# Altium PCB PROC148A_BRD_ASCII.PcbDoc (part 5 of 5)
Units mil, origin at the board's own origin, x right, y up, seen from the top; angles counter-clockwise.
Board outline 7150 x 3764 mil, 4 copper layers (Top Layer, GND01, PWR/GND02, Bottom Layer), stack 60.96 mil thick; 312 components, 352 nets, 2206 pads, 423 vias.
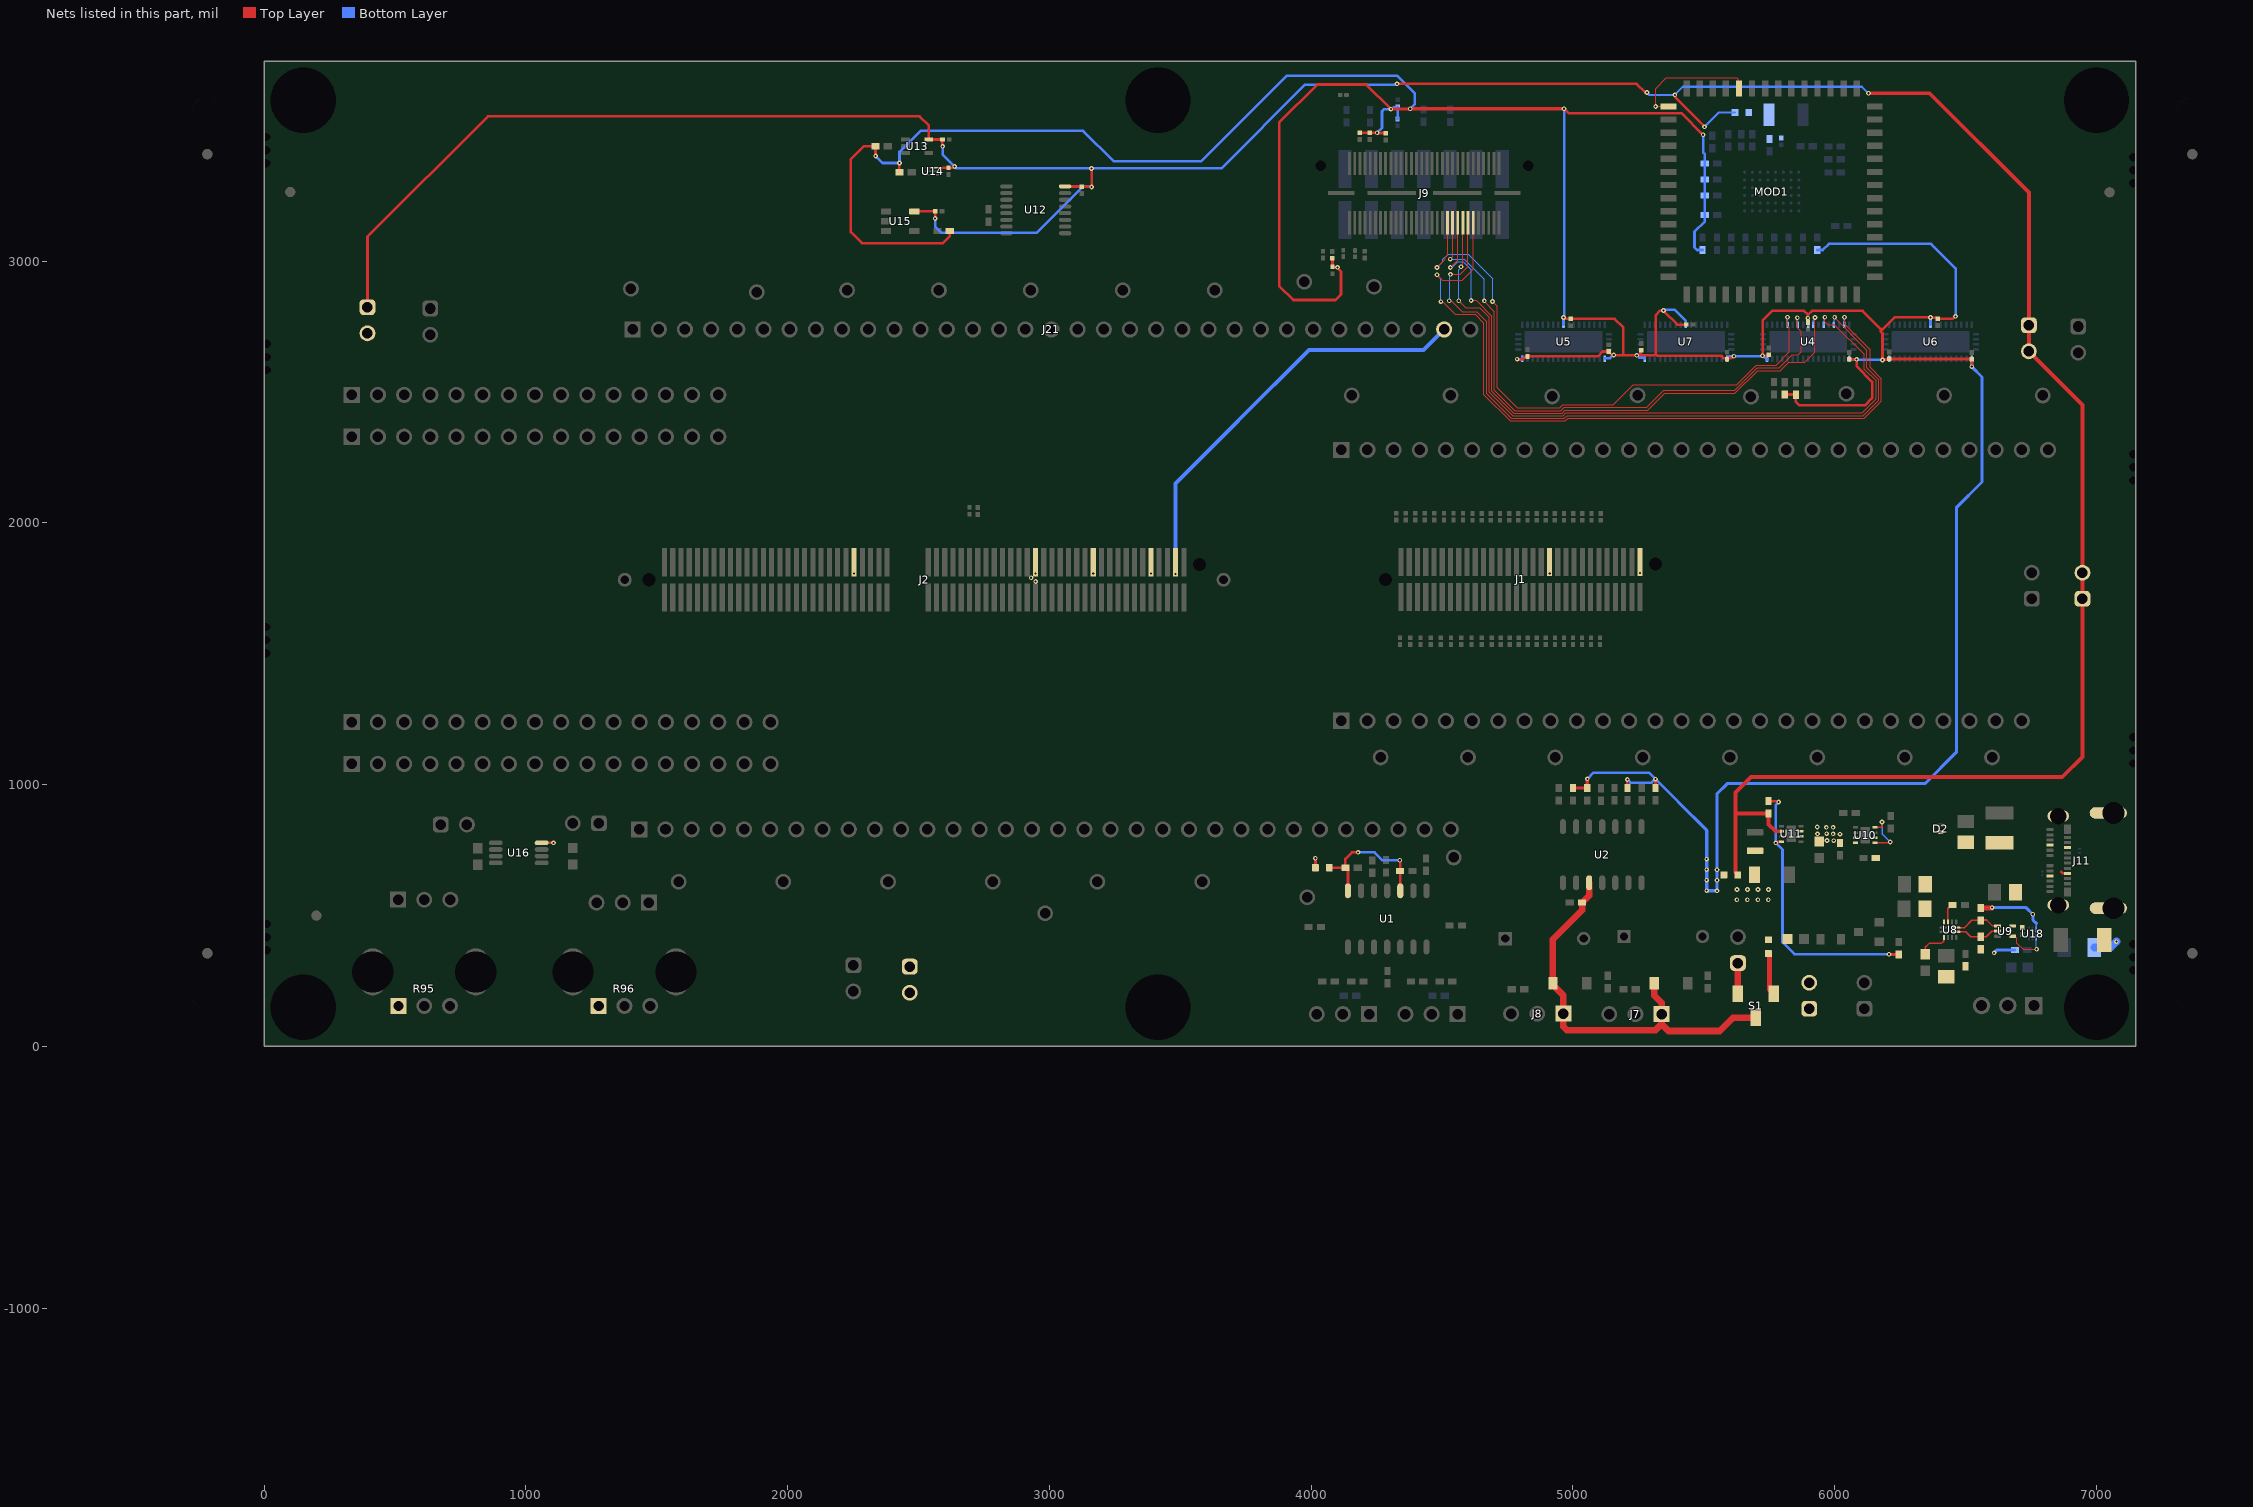
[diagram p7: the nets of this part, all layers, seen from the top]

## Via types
v1: diameter 18, hole 8, Top Layer to Bottom Layer, tented both sides, 422 vias
v2: diameter 18, hole 8, Top Layer to Bottom Layer, 1 vias

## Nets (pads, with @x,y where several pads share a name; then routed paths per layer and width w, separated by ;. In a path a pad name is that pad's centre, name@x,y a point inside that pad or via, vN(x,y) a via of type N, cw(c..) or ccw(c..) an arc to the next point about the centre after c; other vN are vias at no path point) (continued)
TRC_DATA10_MUX: J9.39 U4.26 | length 2289.2
  Top Layer w4: v1(4481,2975.65) 4512.4,3007.05 4512.4,3015.38 4520.86,3023.84 J9.39@4520.86,3147.3 ; v1(4692.97,2845.6) 4710.24,2828.33 4710.24,2516.39 4786.96,2439.67 4950.47,2439.67 4961.93,2451.13 5153.58,2451.13 5230.29,2527.84 5625.99,2527.84 5700.86,2602.71 5775.82,2602.71 5826.31,2653.2 5826.31,2745.54 5819.6,2752.25 v1(5819.6,2785.7)
  Bottom Layer w4: v1(4481,2975.65) 4503.64,2998.29 4503.64,3006.62 4523.45,3026.43 4599.71,3026.43 4692.97,2933.17 v1(4692.97,2845.6) ; v1(5819.6,2785.7) 5819.6,2757.22 U4.26@5819.98,2756.84
TRC_DATA11_MUX: J9.41 U4.28 | length 2207.2
  Top Layer w4: v1(4531.27,3007.56) 4540.54,3016.83 J9.41@4540.54,3147.3 ; v1(4661.71,2848.05) 4661.71,2845.87 4700.24,2807.34 4700.24,2506.53 4777.52,2429.25 4954.19,2429.25 4966.07,2441.13 5281.06,2441.13 5346.41,2506.48 5618.21,2506.48 5702.5,2590.77 5703.66,2590.77 5704.66,2591.77 5788.2,2591.77 5838.08,2641.65 5860.82,2641.65 5872.37,2653.2 5872.37,2730.56 5857.4,2745.53 v1(5857.4,2783.8)
  Bottom Layer w4: v1(4531.27,3007.56) 4584.46,3007.56 4661.71,2930.31 v1(4661.71,2848.05) ; v1(5857.4,2783.8) 5857.4,2758.79 U4.28@5859.35,2756.84
TRC_DATA12_MUX: J9.43 U4.31 | length 2321
  Top Layer w4: v1(4531.54,2975.48) 4560.23,3004.17 J9.43@4560.23,3147.3 ; v1(4611.25,2849.56) 4630.51,2849.56 4690.24,2789.83 4690.24,2502.38 4773.36,2419.25 4958.34,2419.25 4969.12,2430.04 5285.86,2430.04 5350.34,2494.52 5618.98,2494.52 5706.23,2581.77 5792.34,2581.77 5823.55,2612.97 5885,2612.97 5924.48,2652.45 v1(5924.48,2784.53)
  Bottom Layer w4: v1(4531.54,2975.48) 4537.21,2975.48 4559.05,2997.32 4580.56,2997.32 4611.25,2966.63 v1(4611.25,2849.56) ; U4.31@5918.4,2756.84 5918.4,2774.66 5924.48,2780.74 v1(5924.48,2784.53)
TRC_DATA13_MUX: J9.45 U4.33 | length 2716
  Top Layer w4: v1(4563.67,2848.76) 4591.07,2821.36 4644.57,2821.36 4680.24,2785.69 4680.24,2498.24 4769.22,2409.25 4962.48,2409.25 4973.27,2420.04 6104.65,2420.04 6158.12,2473.51 6158.12,2542.55 6112.81,2587.85 6112.81,2643.86 5999.17,2757.5 5973.23,2757.5 5962.23,2768.51 v1(5962.23,2785.71) ; v1(4572.74,2978.45) 4579.91,2985.62 J9.45@4579.91,3147.3
  Bottom Layer w4: v1(4563.67,2848.76) 4563.67,2966.31 4572.74,2975.38 v1(4572.74,2978.45) ; U4.33@5957.77,2756.84 5960,2759.07 5960,2783.48 v1(5962.23,2785.71)
TRC_DATA14_MUX: J9.47 U4.35 | length 2783.9
  Top Layer w4: v1(4527.39,2848.76) 4530.07,2846.08 4537.7,2846.08 4576.44,2807.34 4631.69,2807.34 4670.24,2768.79 4670.24,2493.53 4764.52,2399.25 4966.62,2399.25 4977.41,2410.04 6108.79,2410.04 6168.12,2469.37 6168.12,2546.69 6122.71,2592.1 6122.71,2660.15 5999.98,2782.87 v1(5999.98,2785.71) ; v1(4532.45,2949.48) 4570.46,2949.48 4598.68,2977.7 4598.68,3146.39 J9.47@4599.6,3147.3
  Bottom Layer w4: v1(4527.39,2848.76) 4529.92,2851.29 4529.92,2946.95 v1(4532.45,2949.48) ; U4.35@5997.14,2756.84 5998.56,2758.26 5998.56,2784.29 v1(5999.98,2785.71)
TRC_DATA15_MUX: J9.49 U4.37 | length 2922.5
  Top Layer w4: v1(4480.7,2947.99) 4500.98,2927.71 4577.85,2927.71 4619.28,2969.13 J9.49@4619.28,3147.3 ; v1(4495.56,2845.27) 4498.24,2842.59 4504.17,2842.59 4550.59,2796.18 4627.28,2796.18 4660.24,2763.22 4660.24,2489.39 4760.37,2389.25 4970.76,2389.25 4981.55,2400.04 6112.93,2400.04 6178.16,2465.27 6178.16,2550.79 6134.84,2594.11 6134.84,2662.16 6037.73,2759.26 v1(6037.73,2785.71)
  Bottom Layer w4: v1(4480.7,2947.99) 4495.56,2933.13 v1(4495.56,2845.27) ; U4.37@6036.51,2756.84 6037.12,2757.45 6037.12,2785.1 v1(6037.73,2785.71)
TUSB_EN_N: R53.2 U8.11 | length 74.7
  Top Layer w6: U8.11@6432.72,475.46 6432.13,476.06 6432.13,525.7 6446.45,540.03 R53.2@6450.39,540.03
TUSB_OUT1: R50.2 U8.8 U9.1 | length 177.3
  Top Layer w6: U8.8@6466.18,453.81 6495.81,453.81 6523.57,481.57 R50.2@6557.59,481.57 6559.08,483.06 6580,483.06 6602.69,460.37 U9.1@6622,460.37
TUSB_OUT2: R49.2 U8.7 U9.2 | length 172.7
  Top Layer w6: U8.7@6466.18,438.06 6500.87,438.06 6520,418.94 R49.2@6557.59,418.94 6578.94,418.94 6599.81,439.81 6621.13,439.81 U9.2@6622,440.68
TUSB_PORT: R52.1 U8.3 | length 122.2
  Top Layer w6: R52.1@6346,351.69 6346,379 6360.43,393.43 6408.4,393.43 6416.97,402 U8.3@6416.97,416.41
USBC_EARTH: C34.2 J11.1 J11.2 J11.3 J11.4 R57.1 | length 93.7
  Bottom Layer w30: R57.1@6991.8,377.36 7053.06,377.36 v1(7076,400.31)
USBC_EN: U9.4 U18.1 | length 167.5
  Top Layer w4: U9.4@6680.27,421 6687.55,421 6696.09,412.46 6696.09,394.42 6719.36,371.15 v1(6771.35,371.15)
  Bottom Layer w4: U18.1@6769.74,415.65 6770.54,414.85 6770.54,371.96 v1(6771.35,371.15)
VBAT_LIN: J4.1 S1.3 | length 118.1
  Top Layer w4: J4.1@5629.32,317.2 J4.1@5630.35,318.23
  Top Layer w25: S1.3@5629.32,200.55 J4.1@5629.32,317.2
VBUS_USBC: C8.1 C26.1 C27.1 C28.1 C29.1 C35.1 C43.1 D2.1 J11.A4 J11.A9 J11.B4 J11.B9 R49.1 R50.1 R51.1 R54.1 R94.1 U8.12 U9.5 U10.1 U10.2 U10.4 U18.6 | length 576.2
  Top Layer w6: U10.1@6154.22,777.71 6208.85,777.71 v1(6212.26,781.12) ; U10.4@6154.22,836.76 6175.76,836.76 6181,842 v1(6181,857)
  Top Layer w10: 6865,667.26 6870.57,661.69 6887.95,661.69 J11.B9@6888.86,660.79
  Top Layer w20: R50.1@6557.59,528.82 6599.96,528.82 v1(6601.3,530.16)
  Bottom Layer w6: v1(6181,857) 6181,812.38 v1(6212.26,781.12) ; U18.6@6769.74,447.15 6769.74,470.41
  Bottom Layer w12: v1(6601.3,530.16) 6731.27,530.16 6757.63,503.8 6757.63,482.52 6769.74,470.41 ; v1(6609.26,357.37) 6620.89,369 R94.1@6688.67,369
  other v1: 6756.48,504.95
VCC_3V3_IO: C11.1 C12.1 C13.1 C14.1 C15.1 C16.1 C17.1 C18.1 C19.1 C20.1 C21.1 C22.1 C23.1 C24.1 C25.1 FB4.2 R13.2 R14.2 R15.2 R16.2 R17.2 R23.2 R73.2 R74.2 R75.2 R76.2 R77.2 R78.2 R79.2 R80.2 R83.2 R85.2 R86.2 R87.1 R90.1 U4.1 U4.17 U4.30 U5.1 U5.17 U5.30 U6.1 U6.17 U6.30 U7.1 U7.17 U7.30 | length 16744.5
  Top Layer w10: v1(2336.34,3401.46) 2335.67,3402.13 R79.2@2335.67,3438.96 2290.93,3438.96 2241.53,3389.56 2241.53,3110.92 2283.54,3068.91 2592.94,3068.91 2619.65,3095.62 R83.2@2619.65,3115.05 ; R80.2@2427.05,3339.55 2427.05,3374.71 v1(2427.33,3374.99) ; R15.2@4081.19,3011.2 4081.44,3010.95 4081.44,2978.4 C24.1@4081.68,2978.15 4083.69,2976.14 v1(4100.52,2976.14) 4100.52,2973.98 4114.21,2960.29 4114.21,2872.68 4092.84,2851.31 3932.04,2851.31 3878.03,2905.32 3878.03,3529.44 4023.48,3674.89 4210.24,3674.89 v1(4304.51,3580.61) 4305.21,3581.31 4377.71,3581.31 v1(4378.4,3582) ; R17.2@4186.1,3490.5 R16.2@4223.99,3490.5 v1(4252.03,3490.5) 4253.01,3489.52 4283.9,3489.52 C23.1@4284.88,3488.54 ; v1(4786.87,2625.65) 4809.79,2625.65 4823.17,2639.03 C15.1@4826.2,2636 ; C15.1@4826.52,2636.32 5094.83,2636.32 5113.06,2654.56 C14.1@5137.39,2654.56 5137.39,2653.77 5148.04,2643.12 5154.5,2643.12 v1(5156.03,2641.59) 5157.19,2640.43 5180.03,2640.43 5180.56,2639.9 5191.52,2639.9 ; v1(4964.3,2785) 4969.12,2780.18 4991.7,2780.18 C16.1@4991.7,2779.39 5159.51,2779.39 5191.52,2747.38 5191.52,2639.9 ; v1(4966.12,3582) 4967.14,3582 4983.6,3565.54 5414.61,3565.54 v1(5497.44,3482.71) ; R87.1@5207.87,987.24 v1(5207.87,1019.88) ; C21.1@5261.18,2659.51 5257.91,2656.24 5257.91,2645.31 v1@5252.5,2639.9 ; R85.2@5315.34,987.24 v1(5315.34,1020.91) ; C22.1@5433.11,2757.6 5398.92,2757.6 5346.18,2810.34 v1(5346.18,2811.74) 5344.95,2810.51 5333.47,2810.51 5315.95,2792.99 5315.95,2645.99 ; C20.1@5588.8,2625.41 C20.1@5588.8,2626.2 ; v1(5614.7,2636.7) 5612.54,2636.7 5605.3,2629.46 5592.07,2629.46 C20.1@5588.8,2626.2 ; C12.1@5748.48,2641.86 5748.48,2641.59 5745.21,2638.32 v1(5724.52,2638.32) 5724.52,2773.52 5761.22,2810.22 5883.42,2810.22 5897.5,2796.14 v1(5897.5,2782) 5897.6,2781.9 5897.6,2765.49 C13.1@5897.7,2765.39 ; R13.2@5809.01,2490.38 5850.97,2490.38 R14.2@5851.61,2489.74 5851.61,2462.26 5864.83,2449.04 6115.26,2449.04 6143.4,2477.18 6143.4,2538.88 6083.72,2598.56 v1(6083.72,2624.73) 6083.09,2625.36 C11.1@6056.15,2625.36 ; 5898.32,2795.12 5913.43,2810.22 6106.18,2810.22 6175.33,2741.07 6175.33,2731.43 ; v1(6461.72,2789.05) 6459.56,2789.05 6450.27,2779.76 C19.1@6393.6,2779.76 6390.34,2783.03 6370.34,2783.03 6368.37,2785 v1(6366.2,2785) 6228.9,2785 6175.33,2731.43 ; v1@6523.45,2596.75 C17.1@6523.45,2625.36 6522.69,2626.12 6209.34,2626.12 C18.1@6208.57,2626.89 6205.62,2623.94 6184.11,2623.94 v1(6182.58,2622.41) 6182.58,2724.18 6175.33,2731.43 ; 5191.52,2639.9 v1(5243.77,2639.9) v1@5252.5,2639.9 ; v1@5252.5,2639.9 5309.86,2639.9 5315.95,2645.99 ; 5315.95,2645.99 5323.28,2638.65 5567.66,2638.65 5567.66,2637 5575.2,2629.46 5588.8,2629.46 C20.1@5588.8,2626.2
  Top Layer w12: v1(4378.4,3582) v1(4966.12,3582) ; R90.1@4999.88,986.78 R86.2@5054.88,986.78 v1(5054.88,1022.39)
  Bottom Layer w10: v1(2336.34,3401.46) 2362.81,3374.99 v1(2427.33,3374.99) 2427.33,3417.41 2507.91,3497.99 3129.14,3497.99 3245.53,3381.6 3580.15,3381.6 3906.8,3708.25 4328.32,3708.25 4395.28,3641.29 4395.28,3598.88 v1(4378.4,3582) ; v1(4252.03,3490.5) 4270.72,3509.19 4270.72,3572.18 4279.15,3580.61 v1(4304.51,3580.61) ; v1@4306.68,3580.61 v1(4304.51,3580.61) ; R23.2@4329.6,3542.98 4330.16,3543.54 C25.1@4330.16,3589.58 ; C25.1@4330.71,3590.13 C25.1@4330.16,3589.58 ; v1(4786.87,2625.65) 4806.64,2625.65 U5.17@4806.64,2626.92 U5.17@4806.64,2633.65 ; U5.30@4964.12,2756.84 4964.12,2784.82 v1(4964.3,2785) 4966.12,2786.82 v1(4966.12,3582) ; v1(5054.88,1022.39) 5078.25,1045.76 5290.49,1045.76 v1(5315.34,1020.91) ; U5.1@5121.6,2626.92 5121.6,2629.32 5121.68,2629.4 5141.68,2629.4 5153.87,2641.59 v1(5156.03,2641.59) ; v1(5207.87,1019.88) 5220.08,1007.68 5299.94,1007.68 5313.17,1020.91 v1(5315.34,1020.91) ; v1(5243.77,2639.9) 5245.93,2639.9 5253.86,2631.98 5273.86,2631.98 5273.94,2631.9 U7.17@5273.94,2626.92 ; v1(5346.18,2811.74) 5347.71,2813.27 5353.37,2813.27 5354.92,2814.83 5387.54,2814.83 5431.34,2771.02 5431.34,2756.92 U7.30@5431.42,2756.84 ; 5404.4,931.85 v1(5315.34,1020.91) ; R78.2@5495.22,3042.66 5473.73,3042.66 5464.23,3052.16 5464.23,3112.48 5503.9,3152.15 R73.2@5503.9,3176.5 5504,3176.6 R75.2@5504,3250.4 R77.2@5504,3311.9 R76.2@5504,3373.4 5504,3409.39 5497.68,3415.71 v1@5497.68,3482.47 ; U7.1@5588.9,2626.92 5598.68,2636.7 v1(5614.7,2636.7) 5614.95,2636.95 5723.15,2636.95 v1(5724.52,2638.32) 5726.06,2638.32 5741.16,2623.22 5741.24,2623.3 U4.17@5741.24,2626.92 ; v1(5897.5,2782) 5898.64,2780.86 5898.64,2756.92 U4.30@5898.72,2756.84 ; R74.2@5933.53,3042.66 5953.98,3042.66 5977.32,3066 6368.1,3066 6461.72,2972.38 v1(6461.72,2789.05) ; U4.1@6056.2,2626.92 6058.39,2624.73 v1(6083.72,2624.73) 6084.88,2623.57 6181.42,2623.57 v1(6182.58,2622.41) 6184.11,2623.94 6208.46,2623.94 6208.54,2624.02 U6.17@6208.54,2626.92 ; U6.30@6366.02,2756.84 6366.02,2784.82 v1(6366.2,2785) ; v1(4304.51,3580.61) 4306.04,3582.14 4309.4,3582.14 4314.79,3587.53 4328.11,3587.53 C25.1@4330.16,3589.58
  Bottom Layer w12: 5404.4,931.85 5511,825.25 v1(5511,715.45) v1(5511,675.3) v1(5511,635.15) v1(5511,595) 5511.23,594.77 5549.77,594.77 v1(5550,594.55) v1(5550,634.7) v1(5550,674.85) 5550,964.49 5589.67,1004.16 6344.95,1004.16 6464.79,1124 6464.79,2058.51 6562.71,2156.43 6562.71,2557.49 v1(6523.5,2596.7) U6.1@6523.5,2626.92
VCC_3V3_PG: R56.2 R58.2 U11.8 | length 1079.4
  Top Layer w10: R58.2@5746.82,937.2 5782.68,937.2 v1(5785.82,934.06) ; v1(5774.91,777.66) 5779.72,782.47 5796.93,782.47 U11.8@5797.01,782.55
  Top Layer w12: v1(6207.67,352.27) 6208.56,351.38 R56.2@6245,351.38
  Bottom Layer w10: v1(5785.82,934.06) 5774.91,923.15 v1(5774.91,777.66) 5800.41,752.16 5800.41,398.18 5846.32,352.27 v1(6207.67,352.27)
VCC_3V3_SYS: C32.1 C37.1 C38.1 C39.1 C40.1 FB3.1 FB4.1 J16.1 J16.2 J23.1 J23.2 J28.1 J28.2 J29.1 J29.2 L1.2 R58.1 R95.1 R96.1 U11.6 U12.16 U13.5 U14.6 U15.5 U16.8 | length 12871.6
  Top Layer w6: U14.6@2569.29,3357.11 2590.86,3357.11
  Top Layer w10: J28.1@395,2824 395,3093.44 395.17,3093.27 854.84,3552.94 2504.68,3552.94 2539.29,3518.33 U13.5@2539.29,3464.55 C38.1@2591.3,3464.55 2591.3,3439.37 v1(2592.36,3438.31) ; U16.8@1060.36,777.89 v1(1105.51,777.89) ; U15.5@2483.91,3189.17 U15.5@2484.29,3189.55 2484.79,3190.05 2563.47,3190.05 2563.97,3190.55 2563.97,3163 v1(2563.64,3162.67) ; 2590.86,3357.11 C39.1@2614.29,3357.11 ; C39.1@2614.73,3356.67 2633.29,3356.67 v1(2637.94,3361.32) ; U12.16@3060.12,3285.5 3060.58,3285.03 3123.72,3285.03 C37.1@3124.18,3284.57 3160.4,3284.57 v1(3161.53,3283.44) 3161.53,3353.58 v1(3161.02,3354.09) ; v1(4328.32,3677.32) 5243.5,3677.32 5277.04,3643.78 v1(5282.63,3643.78) ; v1(5389.48,3635.26) 5391.01,3633.73 5391.01,3625.95 5502.79,3514.17 v1(5502.79,3512.97)
  Top Layer w12: C39.1@2614.29,3357.11 C39.1@2614.73,3356.67
  Top Layer w15: FB4.1@5630,655 5621.12,663.88 5621.12,888.25 ; U11.6@5797.01,821.92 5773.08,821.92 5746.82,848.18 R58.1@5746.82,889.95 5622.83,889.95 5621.12,888.25 ; v1(6129.13,3641.22) 6362.28,3641.22 6741.81,3261.69 J23.1@6741.81,2755.22 J23.2@6741.81,2655.22 6946.42,2450.61 J16.2@6946.42,1809.98 J16.1@6946.42,1709.98 6946.42,1106.42 6869.3,1029.3 5681,1029.3 5621.12,969.42 5621.12,888.25
  Bottom Layer w8: v1(5282.63,3643.78) 5291.15,3635.26 v1(5389.48,3635.26) 5420.22,3666 6104.03,3666 6128.81,3641.22 v1(6129.13,3641.22) ; v1(5502.79,3512.97) 5557.64,3567.82 FB3.1@5618.92,3567.82
  Bottom Layer w10: v1(2563.64,3162.67) 2563.64,3131.59 2586.95,3108.28 2950.75,3108.28 3125.91,3283.44 v1(3161.53,3283.44) ; v1(2592.36,3438.31) 2592.36,3406.9 v1(2637.94,3361.32) 2645.17,3354.09 v1(3161.02,3354.09) 3657.3,3354.09 3977.36,3674.15 4325.15,3674.15 v1(4328.32,3677.32)
  other v1: 5626,560.53 5666.15,560.53 5706.3,560.53 5746.45,560.53 5626.45,599.53 5666.6,599.53 5706.76,599.53 5746.91,599.53
VCC_5V0_LIN: FB6.2 S1.1 | length 162.6
  Top Layer w20: FB6.2@5746.82,354.73 5750.43,351.12 5750.43,217.24 S1.1@5767.12,200.55
VCC_5V0_MCAN: C1.1 C2.1 FB5.2 U1.3 U1.7 | length 536.8
  Top Layer w10: FB5.2@4069.6,682.92 C2.1@4130.78,682.92 ; U1.7@4140.64,594.55 4140.64,676.11 4133.83,682.92 C2.1@4130.78,682.92 ; v1(4179.45,741.31) 4155.95,741.31 4130.78,716.14 C2.1@4130.78,682.92 ; v1(4338.57,711.11) 4339.68,710 C1.1@4339.68,670.72 4340.64,669.76 U1.3@4340.64,594.55
  Bottom Layer w10: v1(4179.45,741.31) 4242.55,741.31 4272.75,711.11 v1(4338.57,711.11)
VDD_3V3_PSRAM: C9.1 C10.1 FB3.2 R11.2
VDD_3V3_SYS: MOD1.1 MOD1.52 | length 488.8
  Top Layer w4: MOD1.1@5365.59,3590.66 v1(5315.93,3590.66) 5315.93,3658.73 5357.41,3700.21 5625.11,3700.21 5634.29,3691.03 MOD1.52@5634.29,3659.36 MOD1.52@5634.26,3659.31
VLIN: C5.1 D1.2 D6.2 J7.1 J8.1 S1.2 U2.10 | length 1572.5
  Top Layer w25: U2.10@5061.97,625.17 5061.97,576.18 C5.1@5035.1,549.3 5035.1,520.39 4923.75,409.04 D6.2@4923.75,240.72 4923.75,234.72 4963.69,194.78 J8.1@4963.69,125 4963.69,74.81 4976,62.5 5315.7,62.5 5338.62,85.42 ; D1.2@5310,240.72 5310,195.2 5338.62,166.58 J7.1@5338.62,123.66 5338.62,85.42 ; S1.2@5698.22,110 5611.52,110 5560.52,59 5365.04,59 5338.62,85.42
VMAIN: C33.2 C36.1 FB5.1 FB6.1 J1.158 J1.180 J2.48 J2.84 J2.98 J2.112 J2.118 J19.1 J19.2 J21.32 R55.2 U10.7 U10.8 U11.2 U11.3 | length 1957.3
  Top Layer w10: v1(2254.01,1805.95) J2.48@2254.01,1849.59 ; v1(2946.93,1805.95) J2.84@2946.93,1849.59 ; v1(3167.4,1805.95) J2.98@3167.4,1849.59 ; v1(3387.87,1805.95) J2.112@3387.87,1849.59 ; v1(3481.94,1805.53) 3481.94,1849.17 J2.118@3482.36,1849.59 ; v1(4016.15,718.78) 4016.45,718.48 FB5.1@4016.45,682.92 ; J1.158@4910.24,1850.93 4911.46,1849.71 v1(4911.46,1806.06) ; v1(5256.69,1809.1) J1.180@5256.69,1850.93
  Bottom Layer w15: v1(3481.94,1805.53) 3481.94,2151.08 3720.63,2389.77 3720.63,2390.15 3991.18,2660.7 4429.65,2660.7 J21.32@4507.95,2739
  other v1: 5996.19,786 5970.19,787 6020.19,811 5934.19,812 5994.19,812 5969.19,813 5968.19,837 5994.19,837 5933.19,838 2947.52,1776.44 2930.37,1790.33
pads on no net: D2.1S D2.2S Designator2. Designator2_1. Designator3. Designator3_1. Designator4. Designator4_1. Designator5. Designator5_1. Designator59_3_1_2. Designator59_3_1_2_1. Designator59_3_1_2_2. Designator59_3_1_2_3. Designator64_2_1_2. Designator64_2_1_2_1. Designator64_2_1_2_2. Designator64_2_1_2_3. Designator69_2. Designator69_2_1. Designator69_2_2. Designator69_2_3. FID1.1 FID2.1 FID3.1 FID4.1 FID5.1 FID6.1 J1.61 J1.62 J2.1 J2.2 J2.4 J2.181 J2.182 J2.185 J2.186 J9.8 J9.9 J9.10 J9.11 J9.14 J9.18 J9.20 J9.22 J9.24 J9.26 J9.28 J9.30 J9.32 J9.34 J9.36 J9.38 J9.40 J9.42 J9.44 J9.46 J9.48 J9.50 J9.51 J9.52 J9.53 J9.54 J9.55 J9.56 J9.59 J9.60 J9.MH1 J9.MH2 J10.2 J10.6 J10.13 J10.14 J11.A2 J11.A3 J11.A6 J11.A7 J11.A8 J11.A10 J11.A11 J11.B2 J11.B3 J11.B6 J11.B7 J11.B8 J11.B10 J11.B11 MHNP1. MHNP2. MHNP3. MHNP4. MHNP5. MHNP6. MOD1.53 R95.4 R95.5 R96.4 R96.5 SH-J1.0 SH-J2.0 SH-J3.0 SH-J4.0 SW3.1 U2.6 U2.11 U2.12 U2.14 U4.39 U4.41 U5.18 U5.20 U5.22 U5.24 U5.26 U5.28 U5.31 U5.33 U5.35 U5.37 U5.40 U5.42 U6.18 U6.20 U6.22 U6.24 U6.26 U6.28 U6.31 U6.33 U6.35 U6.37 U6.40 U6.42 U7.18 U7.20 U7.22 U7.24 U7.26 U7.28 U8.5 U8.9 U11.9@5834.41,794.36 U11.9@5834.41,829.79 U12.5 U12.6 U12.10 U12.11 U12.13 U12.14 U13.1 U14.5 U18.5

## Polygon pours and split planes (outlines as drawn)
GND on Top Layer "Top Layer-GND 4" (solid, remove dead copper, pour order 13): 3.15,3762.2 3.15,0 7151.02,0 7151.02,3761.81 3.94,3761.81
VMAIN on Top Layer "Top Layer-VMAIN 2" (solid, remove dead copper, pour order 12): 2235.62,1933.47 2235.62,1777 2248.69,1763.93 2249.36,1764.6 2974.91,1764.6 2974.91,1804.77 2964.47,1815.21 2278.73,1815.21 2271.55,1822.39 2271.55,1933.47
GND on Top Layer "Top Layer-GND 3" (solid, pour order 11): 6789.29,413.64 6789.29,310.65 6922.42,310.65 6922.42,441.03 6911.46,451.99 6815.17,451.99 6789.29,426.11
VBUS_USBC on Top Layer "Top Layer-VBUS_USBC 1" (solid, remove dead copper, pour order 10): 6624.6,319.02 6688.03,382.45 6688.03,507.05 6587.4,507.05 6589.78,391.78 6588.95,392.61 6543.97,392.61 6530.13,378.77 6530.13,336.27 6516.77,322.91 6483.17,322.91 6452.84,292.58 6386.67,292.58 6385.29,291.06 6385.29,212.49 6559.73,212.49 6624.6,277.36
GND on Top Layer "Top Layer-GND 1" (solid, pour order 9): 6930,607.93 6929.93,608 6854.93,608 6844.82,597.89 6805.03,597.89 6792.77,610.15 6772.06,610.15 6760,598.08 6760,571.59 6769.59,562 6794.44,562 6812.44,580 6868.26,580 6878.26,570 6927.24,570 6941,583.76 6941,601 6935,607
VMAIN on Top Layer "Top Layer-VMAIN 1" (solid, pour order 8): 5718,385 5771.01,385 5787.14,368.87 5787.14,304.86 5832.41,259.59 5832.41,80 5968.19,80 5968.19,249.81 5843,375 5843,447.81 5718,447.81
GND on Top Layer "Top Layer-GND 2" (solid, pour order 7): 6930,812.07 6929.93,812 6854.93,812 6844.82,822.11 6805.03,822.11 6792.77,809.86 6772.06,809.86 6760,821.92 6760,848.41 6769.59,858 6794.44,858 6812.44,840 6868.26,840 6878.26,850 6927.24,850 6941,836.24 6941,819 6935,813
GND on Top Layer "Top Layer-GND" (solid, remove dead copper, pour order 6): 5800,562 5871.81,562 5966.93,466.88 6133.86,466.88 6295.82,466.88 6300,471.06 6300,650 6294.58,655.42 6136.5,655.42 6133.86,658.06 6133.86,848.76 6154.11,869.02 6251.11,869.02 6284.11,836.02 6715,836.02 6715,959.02 6100,959.02 6100,755.66 6085.98,741.64 5904.29,741.64 5890,755.75 5890,779.94 5879.94,790 5855,790 5855,833.73 5884.36,833.73 5884.97,834.34 5884.97,853.41 5884.36,854.02 5785.54,854.02 5784.47,852.94 5784.47,832.83 5815,832.5 5815,780.62 5800,765.62
VCC_3V3_IO on Top Layer "Top Layer-VCC_3V3_IO" (solid, pour order 5): 5593,750 5489,750 5489,558 5593,558
VCC_3V3_SYS on Top Layer "Top Layer-VCC_3V3_SYS" (solid, remove dead copper, pour order 4): 5610,778 5610,551 5756.83,551 5756.83,778
NetL1_1 on Top Layer "Top Layer-NetL1_1" (solid, pour order 3): 5807,794.13 5806.87,794 5662,794 5649,807 5649,841 5663,855 5729,855 5774,810 5808,810 5811,807 5811,794.13
USBC_EARTH on Top Layer "Top Layer-USBC_EARTH" (solid, pour order 2): 6948.91,456.09 6927,478 6809,478 6783.54,503.46 6783.54,551.54 6801,569 6941,569 6964,592 6964,836 6942,858 6808,858 6792,874 6792,941 6823,972 7090,972 7122,940 7122,315 7107,300 6952.49,300 6948.91,303.58
VMAIN on Top Layer "Top Layer-VMAIN" (solid, pour order 1): 5992.36,852.94 5927.51,852.94 5903.15,828.58 5890,828.58 5859.57,828.58 5859.57,795.89 5884.41,795.89 5924.57,755.73 6089.57,755.73 6089.57,804.35 6040.95,804.35
VBUS_USBC on Top Layer "Top Layer-VBUS_USBC" (solid, remove dead copper, pour order 0): 6773.54,493.71 6773.54,637.24 6783.54,647.24 6849.05,647.24 6862.85,661.03 6910,661.03 6910,675.14 6857.11,675.14 6847.27,665.29 6801.03,665.29 6775,691.32 6775,767.24 6860,767.24 6870,757.24 6910,757.24 6910,777.24 6870,777.24 6862.77,784.47 6722.77,784.47 6680,827.24 6270,827.24 6250,807.24 6140,807.24 6140,678 6315,678 6315,466 6421,466 6421,637.24 6650,637.24 6660,627.24 6660,454 6667,447 6724.12,447 6724.12,493.71
GND on Bottom Layer "Bottom Layer-GND 2" (solid, remove dead copper, pour order 22): 1.1,3764 7145.98,3764 7145.98,1.57 0.71,1.57 0.71,3760.63
VCC_3V3_IO on Bottom Layer "VCC_3V3_IO_L04_P021" (solid, remove dead copper, pour order 21): 5423.98,836.59 5566.51,836.59 5566.51,574.32 5423.03,574.32 5423.03,607.59
VCC_3V3_IO on Bottom Layer "VCC_3V3_IO_L04_P020" (solid, remove dead copper, pour order 20): 4287.44,3600.34 4287.44,3533.51 4388.61,3533.51 4388.61,3600.34
VCC_3V3_SYS on Bottom Layer "VCC_3V3_SYS_L04_P019" (solid, pour order 19): 5607.62,620.74 5754.94,620.74 5754.94,532.45 5607.13,532.45
GND on Bottom Layer "Bottom Layer-GND 1" (solid, pour order 18): 5845.66,3583 5845.66,3469.12 5913.4,3469.12 5913.4,3580.42 5910.82,3583
VDD_3V3_PSRAM on Bottom Layer "Bottom Layer-VDD_3V3_PSRAM" (solid, remove dead copper, pour order 17): 5735.8,3486.42 5724.44,3497.78 5724.44,3542.31 5714.74,3552.01 5660.34,3552.01 5655.77,3556.58 5655.77,3578.23 5662.26,3584.72 5791.41,3584.72 5814.56,3561.57 5814.56,3463 5788.13,3463 5772.43,3447.3 5743.14,3447.3 5735.8,3454.64
GND on Bottom Layer "Bottom Layer-GND" (solid, pour order 16): 6792.5,429.53 6789.21,426.24 6789.21,310.65 6901.52,310.65 6922.34,331.47 6922.34,441.03 6911.38,451.99 6815.09,451.99 6792.71,429.61
VCC_3V3_SYS on Bottom Layer "Bottom Layer-VCC_3V3_SYS" (solid, pour order 15): 2384.07,99.2 2684.82,99.2 2684.82,404.7 2675.71,413.81 1302.51,413.81 1157.52,558.8 1157.52,736.5 1103.92,790.1 380.82,790.1 259.92,911 259.92,2518.6 500.72,2759.4 500.72,2977 410.52,3067.2 410.52,3068.5 214.82,3068.5 126.02,2979.7 126.02,800 302.52,623.5 302.52,199 402.32,99.2
JTAG_VTREF on Bottom Layer "Bottom Layer-JTAG_VTREF" (solid, pour order 14): 4284.17,3524.36 4379.92,3524.36 4379.92,3260 4284.17,3260
GND on PWR/GND02 "PWR/GND02-GND" (solid, remove dead copper, pour order 25): -5.1,0 5713.58,0 5713.58,1023.09 7149.92,1023.09 7149.92,3792.3 -5.1,3792.3
VMAIN on PWR/GND02 "PWR/GND02-VMAIN" (solid, remove dead copper, pour order 24): 3865.16,878.46 3865.16,686.24 4052.07,686.24 4052.07,878.46 5773.93,878.46 5773.93,115.46 6031.11,115.46 6082.55,166.9 6082.55,908.78 6081.25,908.78 6081.25,1103.78 5357.73,1103.78 5357.73,1854.79 5168.55,1854.79 5168.55,1103.78 5023.93,1103.78 5023.93,1826.41 4825.38,1826.41 4820.41,1831.38 4813.79,1824.76 4813.79,1103.78 4010.2,1103.78 3732.66,1103.78 3732.66,1933.06 2838.83,1933.06 2838.83,878.46 3733.49,878.46
GND on GND01 "GND01-GND" (solid, remove dead copper, pour order 23): -603.95,4736.05 -603.95,-299.22 7351.25,-299.22 7588.99,-61.48 7588.99,4766.5 -562.7,4766.5 -599.72,4729.48

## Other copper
Top Layer:
  text ".Layer_Name" at 576.92,-858.49 h60
GND01:
  text ".Layer_Name" at 668.42,-871.65 h60
PWR/GND02:
  text ".Layer_Name" at 75.12,-868.9 h60
Bottom Layer:
  text ".Layer_Name" at 576.92,-858.49 h60

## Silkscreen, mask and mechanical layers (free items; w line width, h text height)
Top Overlay:
  region: 1941.49,3723.73 1253.06,3723.73 1253.06,3625.5 1941.49,3625.5
  lines w6: 3850,645 3970,645 3970,710 ; 3945,755 3970,755 3970,710 ; 3985,710 3975,710 3970,710 ; 4040,640 3985,640 3985,755 4300,755
  lines w10: 1115.31,3725.64 1941.49,3725.64 1941.49,3625.64 1115.31,3625.64 1115.31,3725.78 ; 1253.61,3625.5 1253.61,3723.73
  text "SL#" at 1130.72,3654 h70
  text "PROC148A" at 304,3206 h60
  text "TMDSHSECDOCK-AM263" at 85,3095 h60
  text ".Layer_Name" at 576.92,-858.49 h60
Bottom Overlay:
  text ".Layer_Name" at 576.92,-858.49 h60
Top Paste:
  text ".Layer_Name" at 576.92,-858.49 h60
Bottom Paste:
  text ".Layer_Name" at 576.92,-858.49 h60
Top Solder:
  text ".Layer_Name" at 576.92,-858.49 h60
  text ".Layer_Name" at 576.92,-858.49 h60
Bottom Solder:
  text ".Layer_Name" at 576.92,-858.49 h60
M1 Board Outline:
  lines w6: -354.33,0 -277.01,0 -78.74,0 -78.74,10.18 -78.74,3482.22 -78.74,3764.55 -354.33,3764.55 -354.33,10.81 -354.33,0 ; 7228.58,0 7426.85,0 7504.17,0 7504.17,10.81 7504.17,3764.55 7228.58,3764.55 7228.58,3482.22 7228.58,10.18 7228.58,0
  lines w10: -0.08,3445 -0.08,3764 7149.92,3764 7149.92,3450 7149.92,0 -0.08,0 -0.08,3450
  text ".Layer_Name" at 31.02,-779.53 h40
M2 Board Dimensions:
  rectangle: 349.33,-390.95 724.33,-265.95
  rectangle: 224.33,-265.95 349.33,-140.95
  lines w7: 224.33,-265.95 1224.33,-265.95 ; 349.33,-390.95 349.33,-140.95 ; 474.33,-390.95 474.33,-140.95 ; 724.33,-390.95 724.33,-140.95 ; 974.33,-390.95 974.33,-140.95 ; 224.33,-390.95 224.33,-140.95 1224.33,-140.95 1224.33,-390.95 224.33,-390.95
  text ".Layer_Name" at 76.92,-858.49 h60
Top M5 Assembly Top/M6 Assembly Bottom:
  drawing of 207 lines, arcs and shapes, not listed
  text "COMPONENTS MARKED 'DNP' SHOULD NOT BE POPULATED." at 1153.5,-318.5 h60
  text ".VariantName" at 2189,-434 h60
  text "PCB VIEWED FROM TOP SIDE" at -228.58,-655.67 h60
  text "BOARD #:" at 2247.92,-655.67 h60
  text ".PRJ_Number" at 2793.42,-655.67 h60
  text "REV:" at 3637.92,-655.67 h60
  text ".PCB_Rev" at 3929.42,-655.67 h60
  text "SVN REV:" at 4475.92,-655.67 h60
  text ".VersionControl_RevNumber" at 4981.92,-655.67 h60
  text "TID #:" at 2247.92,-859 h60
  text ".TID" at 2793.42,-859 h60
  text "PLOT NAME =" at -228.58,-1064.34 h60
  text ".plot_File_Name" at 576.92,-1064.34 h60
  text "GENERATED    :" at 2249.92,-1064.34 h60
  text ".Print_Date" at 3119.42,-1064.34 h60
  text ".Print_Time" at 3848.42,-1064.34 h60
  text "TEXAS INSTRUMENTS" at 5112.92,-1064.34 h60
Bottom M5 Assembly Top/M6 Assembly Bottom:
  lines w10: -292.58,-727.33 6309.42,-727.33 ; -290.58,-930.67 6309.42,-930.67 ; 1115.42,-1140.5 1115.42,-937.67 ; 1737.42,-727.33 1737.42,-524 ; 2577.42,-727.33 2577.42,-524 ; 3844.42,-1134 3844.42,-524 ; 4733.42,-1134 6308.92,-1134 6308.92,-524 -292.58,-524 -292.58,-1134 2304.42,-1134 6309.42,-1134 6309.42,-524
  text "COMPONENTS MARKED 'DNP' SHOULD NOT BE POPULATED." at 6102,-318 h60
  text ".VariantName" at 5058,-434 h60
  text "ASSEMBLY VARIANT:" at 6097,-434 h60
  text ".VersionControl_RevNumber" at 1035.42,-656.17 h60
  text "SVN REV:" at 1541.42,-656.17 h60
  text ".PCB_Rev" at 2087.92,-656.17 h60
  text "REV:" at 2379.42,-656.17 h60
  text ".PRJ_Number" at 3223.92,-656.17 h60
  text "BOARD #:" at 3769.42,-656.17 h60
  text "PCB VIEWED FROM BOTTOM SIDE" at 6245.92,-656.17 h60
  text ".TID" at 3223.92,-859.5 h60
  text "TID #:" at 3769.42,-859.5 h60
  text "TEXAS INSTRUMENTS" at 904.42,-1064.84 h60
  text ".Print_Time" at 2168.92,-1064.84 h60
  text ".Print_Date" at 2897.92,-1064.84 h60
  text "GENERATED    :" at 3767.42,-1064.84 h60
  text ".plot_File_Name" at 5440.42,-1064.84 h60
  text "PLOT NAME =" at 6245.92,-1064.84 h60
M9 Title Sheet:
  lines w10: -991.58,1041.5 -791.58,1041.5 ; -991.58,3416.5 -791.58,3416.5 ; -991.58,5791.5 -791.58,5791.5 ; 1508.42,-1333.5 1508.42,-1133.5 ; 1508.42,7966.5 1508.42,8166.5 ; 4008.42,-1333.5 4008.42,-1133.5 ; 4008.42,7966.5 4008.42,8166.5 ; 5820.92,-1133.5 5820.92,-523.5 10803.42,-523.5 ; 6508.42,-1333.5 6508.42,-1133.5 ; 6508.42,7966.5 6508.42,8166.5 ; 9008.42,-1333.5 9008.42,-1133.5 ; 9008.42,7966.5 9008.42,8166.5 ; 10803.42,-1133.5 10803.42,-523.5 ; 10803.42,-823.5 13803.42,-823.5 ; 10803.42,-223.5 13803.42,-223.5 ; 10804.42,370.5 13804.42,370.5 ; 11508.42,-1333.5 11508.42,-1133.5 ; 11508.42,7966.5 11508.42,8166.5 ; 12308.42,-1123.5 12308.42,-523.5 ; 13803.42,-523.5 10803.42,-523.5 ; 13803.42,76.5 10803.42,76.5 ; 13808.42,66.5 13808.42,-1133.5 ; 13808.42,871 10804.42,871 10803.42,871 10803.42,370.5 10803.42,76.5 ; 13808.42,1041.5 14008.42,1041.5 ; 13808.42,3416.5 14008.42,3416.5 ; 13808.42,5791.5 14008.42,5791.5 ; 10803.42,-523.5 10803.42,76.5 ; 13808.42,-1133.5 13808.42,7966.5 -791.58,7966.5 -791.58,-1133.5 13808.42,-1133.5 ; -991.58,-1333.5 -991.58,8166.5 14008.42,8166.5 14008.42,-1333.5 -991.58,-1333.5
  text "1" at 239.76,8036.5 h70
  text "2" at 2735.42,8036.5 h70
  text "3" at 5224.76,8036.5 h70
  text "4" at 7731.43,8036.5 h70
  text "5" at 10230.42,8036.5 h70
  text "6" at 12735.42,8036.5 h70
  text "A" at -916.58,6893.5 h70
  text "A" at 13883.42,6893.5 h70
  text "B" at -916.58,4513.5 h70
  text "B" at 13883.42,4513.5 h70
  text "C" at -916.58,2138.5 h70
  text "C" at 13883.42,2138.5 h70
  text "PROJECT TITLE:" at 10843.42,277.5 h45
  text ".PRJ_Title" at 10893.42,144.17 h70
  text "DESIGNED FOR:" at 10843.42,-23.5 h45
  text ".PRJ_Customer" at 10893.42,-163.5 h70
  text "D" at -916.58,-231.5 h70
  text "D" at 13883.42,-231.5 h70
  text "FILE NAME:" at 10843.42,-323.5 h45
  text ".PCB_File_Name_No_Path" at 10893.42,-443.5 h70
  text "Texas Instruments (TI) and/or its licensors do not warrant the accuracy or completeness of this specification" at 5873.92,-605.34 h45
  text "ENGINEER:" at 10843.42,-613.5 h45
  text "LAYOUT BY:" at 12348.42,-613.5 h45
  text "or any information contained therein. TI and/or its licensors do not warrant that this design will meet" at 5828.93,-718 h45
  text ".PRJ_Engineer" at 10893.42,-768.49 h70
  text ".PCB_Layout" at 12398.92,-768.49 h70
  text "the specifications, will be suitable for your application or fit for any particular purpose, or will operate in" at 5828.93,-830.67 h45
  text "ALTIUM DESIGNER VERSION:" at 12348.42,-923.5 h45
  text "an implementation. TI and/or its licensors do not warrant that the design is production worthy. You should" at 5828.93,-943.34 h45
  text "completely validate and test your design implementation to confirm the system functionality for your application." at 5873.92,-1056 h45
  text ".print_Scale" at 10893.42,-1056.83 h70
  text ".Application_BuildNumber" at 12398.92,-1056.83 h70
  text "1" at 239.76,-1263.5 h70
  text "2" at 2735.42,-1263.5 h70
  text "3" at 5224.76,-1263.5 h70
  text "4" at 7731.43,-1263.5 h70
  text "5" at 10230.42,-1263.5 h70
  text "6" at 12735.42,-1263.5 h70
M10 Fab Notes:
  drawing of 189 lines, arcs and shapes, not listed
  text "DESIGN INFORMATION" at 11881.94,6356.17 h60
  text "MIN. TRACK WIDTH:" at 11237.38,6224.05 h60
  text "4" at 12333.62,6224.05 h60
  text "MIL" at 12488.38,6224.05 h60
  text "4" at 12332.62,6101.99 h60
  text "MIN. CLEARANCE:" at 11237.38,6099.92 h60
  text "MIL" at 12488.38,6099.92 h60
  text "MIN. VIA PAD SIZE:" at 11237.38,5975.8 h60
  text "18" at 12303.63,5975.8 h60
  text "MIL" at 12488.38,5975.8 h60
  text "0.12mm (5MIL)" at 11932.38,5845.9 h60
  text "MINIMUM ANNULAR RING" at 10908.15,5837.67 h60
  text "EXTERNAL" at 12640.38,5837.67 h60
  text "PER" at 11108.15,5727.55 h60
  text "IPC-D-275 CLASS 2 LEVEL C" at 11328.15,5727.54 h60
  text "MIL, HOLES" at 12816.38,5627.07 h60
  text "+/-" at 12423.92,5618.48 h60
  text "+/-" at 13277.92,5618.48 h60
  text "REGISTRATION TOLERANCES:" at 10908.15,5617.42 h60
  text "METAL" at 12107.92,5617.42 h60
  text "5" at 12684.12,5617.42 h60
  text "3" at 13517.12,5617.42 h60
  text "MIL" at 13633.38,5617.42 h60
  text "HOLE SIZE TOLERANCE (UNLESS OTHERWISE SPECIFIED):" at 10908.15,5519.1 h60
  text "+/-" at 13277.92,5516.23 h60
  text "3" at 13517.12,5515.17 h60
  text "MIL" at 13633.38,5515.17 h60
  text "MATERIAL:" at 10833.38,5377.52 h60
  text "FR-4 High Tg" at 11819.82,5248.99 h60
  text "X" at 11674.28,5238.95 h60
  text "FR-408" at 11254.38,5236.49 h60
  text "OTHER" at 12742.38,5236.49 h60
  text "62 MIL (1.6mm) +/-10%" at 11574.48,5093.46 h60
  text "X" at 11454.38,5091.01 h60
  text "THICKNESS:" at 10908.15,5085.24 h60
  text "OTHER" at 12859.38,5085.24 h60
  text "TOLERANCE:" at 10908.15,4946.92 h60
  text "X" at 11756.38,4946.92 h60
  text "ANSI IPC-6012 TYPE 3 CLASS 2" at 11934.4,4946.92 h60
  text "OTHER +/-" at 11934.38,4802.73 h60
  text "BOW & TWIST:" at 10908.15,4657.54 h60
  text "X" at 11756.38,4657.54 h60
  text "ANSI IPC-6012 TYPE 3 CLASS 2" at 11934.4,4657.54 h60
  text "OTHER +/-" at 11934.38,4510.85 h60
  text "DRILLING:" at 10833.38,4380.23 h60
  text "NC_DRILL FILES" at 12594.38,4275.04 h60
  text "REFERENCE:" at 10908.15,4271.1 h60
  text "X" at 11565.38,4271.01 h60
  text "AS SHOWN" at 11743.38,4271.1 h60
  text "X" at 12466.38,4271.1 h60
  text "OTHER" at 12892.38,4128.85 h60
  text "PTH COPPER THICKNESS:" at 10907.83,4125.32 h60
  text "X" at 12047.06,4125.32 h60
  text "20-30 um" at 12175.06,4125.32 h60
  text "BOARD FINISH:" at 10833.38,3977.72 h60
  text "SILKSCREEN:" at 10988.6,3867.6 h60
  text "X" at 11946.38,3867.6 h60
  text "TOP" at 12063.38,3867.6 h60
  text "X" at 12456.38,3867.6 h60
  text "BOTTOM" at 12574.38,3867.6 h60
  text "SILKSCREEN COLOR:" at 10988.6,3712.41 h60
  text "X" at 11945.38,3712.41 h60
  text "WHITE" at 12063.38,3712.41 h60
  text "OTHER" at 12574.38,3712.41 h60
  text "X" at 12076.38,3568.96 h60
  text "GREEN" at 12194.38,3568.96 h60
  text "OTHER" at 12812.38,3568.96 h60
  text "SOLDER RESIST COLOR:" at 10988.6,3562.09 h60
  text "X" at 12668,3417 h60
  text "MATTE" at 12194.38,3414.71 h60
  text "SEMI-GLOSS" at 12811.92,3414.07 h60
  text "IMMERSION GOLD (ENIG)" at 11894.38,3241.94 h60
  text "ENEPIG" at 13231.92,3234.72 h60
  text "SURFACE FINISH:" at 10833.38,3233.72 h60
  text "X" at 11716.38,3233.72 h60
  text "IMM. TIN/SILVER OR EQUIV" at 11162.92,3096.4 h60
  text "OTHER" at 12594.38,3092.46 h60
  text "ARRAY/PANEL:" at 10833.38,2937.09 h60
  text "CUT AND TRIM PER M1 BOARD OUTLINE" at 11894.38,2928.86 h60
  text "N.C. ROUTE" at 11894.38,2792.9 h60
  text "Breakaway Tabs" at 12760.38,2792.9 h60
  text "X" at 12580.27,2791.41 h60
  text "CERTIFICATION:" at 10833.38,2663.77 h60
  text "MATERIALS AND WORKMANSHIP FOR ALL PCBS" at 11558.38,2663.77 h60
  text "TO MEET OR EXCEED THE REQUIREMENTS OF:" at 11558.38,2569.71 h60
  text "X" at 11195.89,2441.08 h60
  text "ANSI IPC-A-600F CLASS ->" at 11323.88,2441.08 h60
  text "X" at 12971.89,2441.08 h60
  text "2" at 13081.88,2441.08 h60
  text "1" at 12766.88,2439.58 h60
  text "3" at 13435.88,2439.58 h60
  text "X" at 12007.89,2293.39 h60
  text "RoHS" at 12135.88,2293.39 h60
  text "OTHER" at 12780.28,2293.39 h60
  text "PER ORDER" at 13177.34,2293.39 h60
  text "ALL BOARDS MUST MEET OR EXCEED UL94-V0 REQUIREMENTS." at 10860.92,2139.57 h60
  text "PCB MUST BEAR THE UL94V-0 UL REGISTERED MATERIAL ID NUMBER" at 10860.92,2023.5 h60
  text "ADDITIONAL REQUIREMENTS:" at 10833.38,1854.08 h60
  text "MICROSECTION:" at 10908.15,1746.95 h60
  text "YES" at 11813.88,1746.95 h60
  text "REQUIRED" at 12675.38,1602.62 h60
  text "BARE BOARD ELEC. TEST:" at 10908.15,1599.76 h60
  text "NONE" at 12213.88,1599.76 h60
  text "X" at 12557.38,1599.76 h60
  text "PER ORDER" at 13267.38,1599.76 h60
  text "X" at 10966.5,1451.76 h60
  text "8MIL VIAS REQUIRE NON-CONDUCTIVE FILL AND PLANARIZE" at 10877.94,1384.7 h59
  text "XX MIL VIAS REQUIRE CONDUCTIVE FILL AND PLANARIZE" at 11084.3,1290.84 h60
  text "OUTER XX MIL TRACES REQUIRE 50 OHM SINGLE-ENDED IMPEDANCE" at 11083.31,1127.46 h58
  text "LAYER 2 & 3 (INNER LAYERS) XX MIL WIDE, XX MIL SPACE / TRACES REQUIRE 100 OHM DIFFERENTIAL IMPEDANCE" at 11075.31,891.74 h60
  text ".Layer_Name" at 76.92,-858.49 h60
M11 Gerber Information:
  lines w10: -792.08,-930.17 5807.92,-930.17 ; -792.08,-726.83 5809.92,-726.83 ; -792.08,-523.5 -792.08,-1133.5 3212.92,-1133.5 5809.92,-1133.5 5809.92,-523.5 -791.58,-523.5 -791.58,-1133.5 783.92,-1133.5 ; 1672.92,-1133.5 1672.92,-523.5 ; 2939.92,-726.83 2939.92,-523.5 ; 3779.92,-726.83 3779.92,-523.5 ; 4401.92,-1140 4401.92,-937.17
  text "ALL ARTWORK VIEWED FROM TOP SIDE" at -728.58,-655.67 h60
  text "BOARD #:" at 1747.92,-655.67 h60
  text ".PRJ_Number" at 2293.42,-655.67 h60
  text "REV:" at 3137.92,-655.67 h60
  text ".PCB_Rev" at 3429.42,-655.67 h60
  text "SVN REV:" at 3975.92,-655.67 h60
  text ".VersionControl_RevNumber" at 4481.92,-655.67 h60
  text "LAYER NAME =" at -728.58,-858.49 h60
  text "TID #:" at 1747.92,-859 h60
  text ".TID" at 2293.42,-859 h60
  text "PLOT NAME =" at -728.58,-1064.34 h60
  text ".plot_File_Name" at 76.92,-1064.34 h60
  text "GENERATED    :" at 1749.92,-1064.34 h60
  text ".Print_Date" at 2619.42,-1064.34 h60
  text ".Print_Time" at 3348.42,-1064.34 h60
  text "TEXAS INSTRUMENTS" at 4612.92,-1064.34 h60
M12 Stackup:
  drawing of 318 lines, arcs and shapes, not listed
  text "Layer" at -353.26,5344 h60
  text "Name" at 56.65,5344 h60
  text "Material" at 986.4,5344 h60
  text "Thickness" at 1846.16,5344 h60
  text "Constant" at 2496,5344 h60
  text "Board Layer Stack" at 3065.86,5344 h60
  text "Top Overlay" at 56.65,5224 h60
  text "IMPEDENCE TABLE :" at 5010.35,5143.58 h80
  text "Top Solder" at 56.65,5104 h60
  text "Solder Resist" at 986.4,5104 h60
  text "1.00mil" at 1846.16,5104 h60
  text "3.5" at 2496,5104 h60
  text "1" at -353.26,4984 h60
  text "Top Layer" at 56.65,4984 h60
  text "1.40mil" at 1846.16,4984 h60
  text "LAYER" at 4375.17,4960.13 h70
  text "TRACE WIDTH" at 4662.37,4959.29 h70
  text "SPACING" at 5147.37,4959.29 h70
  text "IMPEDANCE +/- 10%" at 5482.37,4959.29 h70
  text "REFERENCE LAYER" at 6207.37,4959.29 h70
  text "Dielectric 2" at 56.65,4864 h60
  text "FR-4" at 986.4,4864 h60
  text "3.70mil" at 1846.16,4864 h60
  text "4.1" at 2496,4864 h60
  text "TOP" at 4442.25,4801.15 h70
  text "LAYER-3" at 6331.54,4797.21 h65
  text "4 MILS" at 4727.25,4796.15 h65
  text "5 MILS" at 5182.25,4796.15 h65
  text "120OHM" at 5602.25,4796.15 h65
  text "2" at -353.26,4744 h60
  text "GND01" at 56.65,4744 h60
  text "1.38mil" at 1846.16,4744 h60
  text "Dielectric 1" at 56.65,4624 h60
  text "FR-4" at 986.4,4624 h60
  text "48.00mil" at 1846.16,4624 h60
  text "4.8" at 2496,4624 h60
  text "LAYER-2 /LAYER-3" at 6220.94,4614.92 h65
  text "4 MILS" at 4727.25,4611.15 h65
  text "50 OHM" at 5602.25,4611.15 h65
  text "TOP/BOT" at 4332.92,4609.66 h70
  text "-" at 5267.25,4606.15 h65
  text "3" at -353.26,4504 h60
  text "PWR/GND02" at 56.65,4504 h60
  text "1.38mil" at 1846.16,4504 h60
  text "Dielectric 3" at 56.65,4384 h60
  text "FR-4" at 986.4,4384 h60
  text "3.70mil" at 1846.16,4384 h60
  text "4.1" at 2496,4384 h60
  text "4" at -353.26,4264 h60
  text "Bottom Layer" at 56.65,4264 h60
  text "1.40mil" at 1846.16,4264 h60
  text "Bottom Solder" at 56.65,4144 h60
  text "Solder Resist" at 986.4,4144 h60
  text "1.00mil" at 1846.16,4144 h60
  text "3.5" at 2496,4144 h60
  text "Bottom Overlay" at 56.65,4024 h60
  text ".Layer_Name" at 76.92,-858.49 h60
Drill Drawing:
  drawing of 185 lines, arcs and shapes, not listed
  text "Symbol" at -604.32,7872.4 h65.06
  text "Count" at -144.1,7872.4 h65.06
  text "Hole Size" at 399.89,7872.4 h65.06
  text "Plated" at 1449.76,7872.4 h65.06
  text "Drill Layer Pair" at 1909.98,7872.4 h65.06
  text "Hole Tolerance (+)" at 3267,7872.4 h65.06
  text "Hole Tolerance (-)" at 4475.22,7872.4 h65.06
  text "Hole Length" at 5683.43,7872.4 h65.06
  text "422" at -144.1,7736.85 h54.22
  text "8.00mil (0.203mm)" at 399.89,7736.85 h54.22
  text "PTH" at 1449.76,7736.85 h54.22
  text "Top Layer - Bottom Layer" at 1909.98,7736.85 h54.22
  text "3.00mil (0.076mm)" at 3267,7736.85 h54.22
  text "3.00mil (0.076mm)" at 4475.22,7736.85 h54.22
  text "-" at 5683.43,7736.85 h54.22
  text "1" at -144.1,7601.3 h54.22
  text "8.00mil (0.203mm)" at 399.89,7601.3 h54.22
  text "PTH" at 1449.76,7601.3 h54.22
  text "Top Layer - Bottom Layer" at 1909.98,7601.3 h54.22
  text "-" at 5683.43,7601.3 h54.22
  text "4" at -144.1,7465.75 h54.22
  text "31.50mil (0.800mm)" at 399.89,7465.75 h54.22
  text "PTH" at 1449.76,7465.75 h54.22
  text "Top Layer - Bottom Layer" at 1909.98,7465.75 h54.22
  text "3.00mil (0.076mm)" at 3267,7465.75 h54.22
  text "3.00mil (0.076mm)" at 4475.22,7465.75 h54.22
  text "-" at 5683.43,7465.75 h54.22
  text "2" at -144.1,7330.2 h54.22
  text "33.07mil (0.840mm)" at 399.89,7330.2 h54.22
  text "PTH" at 1449.76,7330.2 h54.22
  text "Top Layer - Bottom Layer" at 1909.98,7330.2 h54.22
  text "3.00mil (0.076mm)" at 3267,7330.2 h54.22
  text "3.00mil (0.076mm)" at 4475.22,7330.2 h54.22
  text "-" at 5683.43,7330.2 h54.22
  text "6" at -144.1,7194.65 h54.22
  text "39.37mil (1.000mm)" at 399.89,7194.65 h54.22
  text "PTH" at 1449.76,7194.65 h54.22
  text "Top Layer - Bottom Layer" at 1909.98,7194.65 h54.22
  text "3.00mil (0.076mm)" at 3267,7194.65 h54.22
  text "3.00mil (0.076mm)" at 4475.22,7194.65 h54.22
  text "-" at 5683.43,7194.65 h54.22
  text "262" at -144.1,7059.1 h54.22
  text "40.16mil (1.020mm)" at 399.89,7059.1 h54.22
  text "PTH" at 1449.76,7059.1 h54.22
  text "Top Layer - Bottom Layer" at 1909.98,7059.1 h54.22
  text "3.00mil (0.076mm)" at 3267,7059.1 h54.22
  text "3.00mil (0.076mm)" at 4475.22,7059.1 h54.22
  text "-" at 5683.43,7059.1 h54.22
  text "3" at -144.1,6923.55 h54.22
  text "42.91mil (1.090mm)" at 399.89,6923.55 h54.22
  text "PTH" at 1449.76,6923.55 h54.22
  text "Top Layer - Bottom Layer" at 1909.98,6923.55 h54.22
  text "3.00mil (0.076mm)" at 3267,6923.55 h54.22
  text "3.00mil (0.076mm)" at 4475.22,6923.55 h54.22
  text "-" at 5683.43,6923.55 h54.22
  text "2" at -144.1,6788 h54.22
  text "62.99mil (1.600mm)" at 399.89,6788 h54.22
  text "PTH" at 1449.76,6788 h54.22
  text "Top Layer - Bottom Layer" at 1909.98,6788 h54.22
  text "3.00mil (0.076mm)" at 3267,6788 h54.22
  text "3.00mil (0.076mm)" at 4475.22,6788 h54.22
  text "23.62mil (0.600mm)" at 5683.43,6788 h54.22
  text "2" at -144.1,6652.45 h54.22
  text "82.68mil (2.100mm)" at 399.89,6652.45 h54.22
  text "PTH" at 1449.76,6652.45 h54.22
  text "Top Layer - Bottom Layer" at 1909.98,6652.45 h54.22
  text "3.00mil (0.076mm)" at 3267,6652.45 h54.22
  text "3.00mil (0.076mm)" at 4475.22,6652.45 h54.22
  text "23.62mil (0.600mm)" at 5683.43,6652.45 h54.22
  text "4" at -144.1,6516.9 h54.22
  text "157.48mil (4.000mm)" at 399.89,6516.9 h54.22
  text "PTH" at 1449.76,6516.9 h54.22
  text "Top Layer - Bottom Layer" at 1909.98,6516.9 h54.22
  text "3.00mil (0.076mm)" at 3267,6516.9 h54.22
  text "3.00mil (0.076mm)" at 4475.22,6516.9 h54.22
  text "70.87mil (1.800mm)" at 5683.43,6516.9 h54.22
  text "24" at -144.1,6381.35 h54.22
  text "32.00mil (0.813mm)" at 399.89,6381.35 h54.22
  text "NPTH" at 1449.76,6381.35 h54.22
  text "Top Layer - Bottom Layer" at 1909.98,6381.35 h54.22
  text "3.00mil (0.076mm)" at 3267,6381.35 h54.22
  text "3.00mil (0.076mm)" at 4475.22,6381.35 h54.22
  text "-" at 5683.43,6381.35 h54.22
  text "2" at -144.1,6245.8 h54.22
  text "40.16mil (1.020mm)" at 399.89,6245.8 h54.22
  text "NPTH" at 1449.76,6245.8 h54.22
  text "Top Layer - Bottom Layer" at 1909.98,6245.8 h54.22
  text "3.00mil (0.076mm)" at 3267,6245.8 h54.22
  text "3.00mil (0.076mm)" at 4475.22,6245.8 h54.22
  text "-" at 5683.43,6245.8 h54.22
  text "4" at -144.1,6110.25 h54.22
  text "50.00mil (1.270mm)" at 399.89,6110.25 h54.22
  text "NPTH" at 1449.76,6110.25 h54.22
  text "Top Layer - Bottom Layer" at 1909.98,6110.25 h54.22
  text "3.00mil (0.076mm)" at 3267,6110.25 h54.22
  text "3.00mil (0.076mm)" at 4475.22,6110.25 h54.22
  text "-" at 5683.43,6110.25 h54.22
  text "4" at -144.1,5974.7 h54.22
  text "126.00mil (3.200mm)" at 399.89,5974.7 h54.22
  text "NPTH" at 1449.76,5974.7 h54.22
  text "Top Layer - Bottom Layer" at 1909.98,5974.7 h54.22
  text "3.00mil (0.076mm)" at 3267,5974.7 h54.22
  text "3.00mil (0.076mm)" at 4475.22,5974.7 h54.22
  text "-" at 5683.43,5974.7 h54.22
  text "6" at -144.1,5839.15 h54.22
  text "250.00mil (6.350mm)" at 399.89,5839.15 h54.22
  text "NPTH" at 1449.76,5839.15 h54.22
  text "Top Layer - Bottom Layer" at 1909.98,5839.15 h54.22
  text "3.00mil (0.076mm)" at 3267,5839.15 h54.22
  text "3.00mil (0.076mm)" at 4475.22,5839.15 h54.22
  text "-" at 5683.43,5839.15 h54.22
  text "748 Total" at -144.1,5703.6 h54.22
  text "Slot definitions :" at -604.32,5570.67 h54.22
  text "Routed Path Length" at 331.58,5570.67 h54.22
  text "= Calculated from tool start centre position to tool end centre position." at 1330.72,5570.67 h54.22
  text "Hole Length" at 331.58,5478.4 h54.22
  text "= Routed Path Length + Tool Size = Slot length as defined in the PCB layout" at 960.34,5478.4 h54.22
